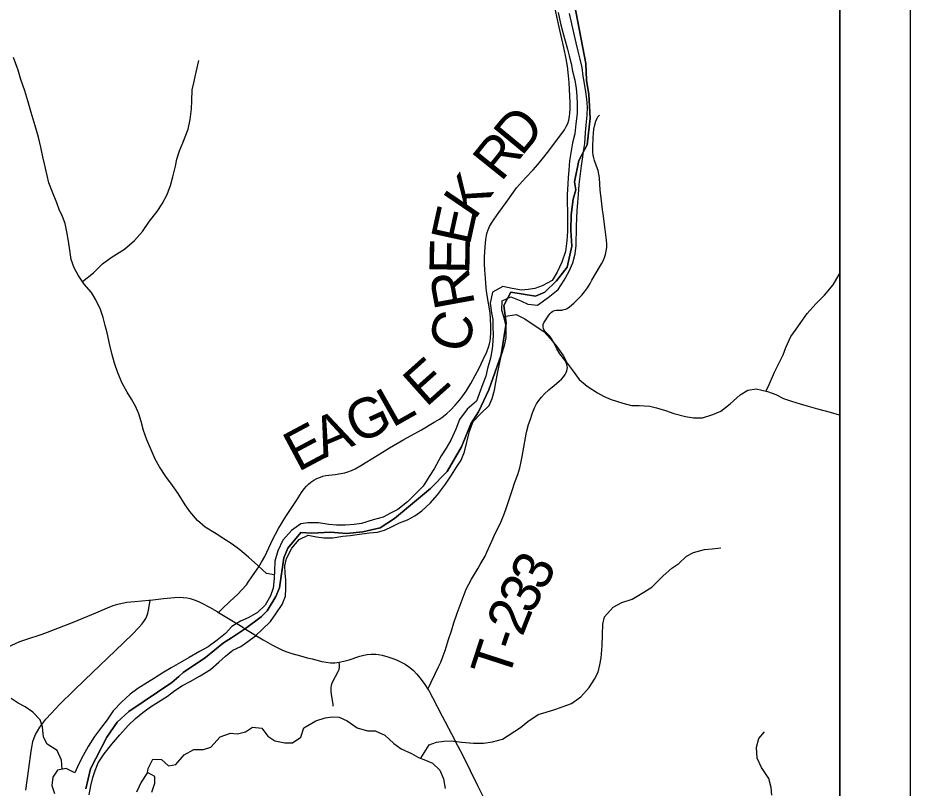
# Model space of a CAD drawing. Extents: x 0 to 34, y 0 to 22.
# Drawn here: x 7.947 to 9.214, y 15.927 to 17.022 of the extents above; entities that cross this region are included whole.
import ezdxf

# ---------------------------------------------------------------- set-up
doc = ezdxf.new("R2010")
doc.units = 0
for name, color, linetype in [('Default', 7, 'Continuous'), ('GM_X_County_Road', 7, 'Continuous'), ('GM_X_Minor_River', 7, 'Continuous'), ('GM_X_Township_Road', 7, 'Continuous'), ('GM_X_Township_Road_Text', 7, 'Continuous'), ('SH_Cut_Line', 7, 'Continuous'), ('SH_Data', 7, 'Continuous')]:
    doc.layers.add(name, color=color, linetype=linetype)

msp = doc.modelspace()

# ---------------------------------------------------------------- linework, layer by layer
at = {"layer": 'Default'}
for points in [[(9.1142, 14.0996), (9.1142, 17.7402)], [(8.735, 17.0537), (8.7536, 16.957), (8.7544, 16.9333), (8.7578, 16.9127), (8.7595, 16.8791), (8.7556, 16.8415), (8.7438, 16.8189), (8.7373, 16.7886), (8.7394, 16.7775), (8.7356, 16.7643), (8.7327, 16.742), (8.732, 16.72), (8.7335, 16.6972), (8.7271, 16.6673), (8.712, 16.6482), (8.6955, 16.6318), (8.6818, 16.6265), (8.6468, 16.632), (8.6371, 16.6129), (8.6404, 16.5881), (8.6333, 16.5428), (8.6156, 16.4931), (8.6011, 16.4621), (8.5903, 16.4448), (8.5769, 16.4122), (8.5565, 16.3771), (8.5331, 16.353), (8.4818, 16.3103), (8.4614, 16.297), (8.4368, 16.2914), (8.4136, 16.2889), (8.3908, 16.2909), (8.3642, 16.2897), (8.3485, 16.2907), (8.3303, 16.2683), (8.3243, 16.2543), (8.3186, 16.2117), (8.3132, 16.1995), (8.3007, 16.1792), (8.2924, 16.1706), (8.2699, 16.1539), (8.2503, 16.1408), (8.2386, 16.1335), (8.2134, 16.1129), (8.1813, 16.0914), (8.1752, 16.086), (8.1652, 16.0772), (8.1042, 16.0361), (8.0876, 16.0208), (8.0731, 15.9995), (8.0499, 15.9547), (8.0431, 15.9261)], [(8.0431, 15.9261), (8.0499, 15.9547), (8.0731, 15.9995), (8.0876, 16.0208), (8.1042, 16.0361), (8.1652, 16.0772), (8.1752, 16.086), (8.1813, 16.0914), (8.2134, 16.1129), (8.2386, 16.1335), (8.2503, 16.1408), (8.2699, 16.1539), (8.2924, 16.1706), (8.3007, 16.1792), (8.3132, 16.1995), (8.3186, 16.2117), (8.3243, 16.2543), (8.3303, 16.2683), (8.3485, 16.2907), (8.3642, 16.2897), (8.3908, 16.2909), (8.4136, 16.2889), (8.4368, 16.2914), (8.4614, 16.297), (8.4818, 16.3103), (8.5331, 16.353), (8.5565, 16.3771), (8.5769, 16.4122), (8.5903, 16.4448), (8.6011, 16.4621), (8.6156, 16.4931), (8.6333, 16.5428), (8.6404, 16.5881), (8.6371, 16.6129), (8.6468, 16.632), (8.6818, 16.6265), (8.6955, 16.6318), (8.712, 16.6482), (8.7271, 16.6673), (8.7335, 16.6972), (8.732, 16.72), (8.7327, 16.742), (8.7356, 16.7643), (8.7394, 16.7775), (8.7373, 16.7886), (8.7438, 16.8189), (8.7556, 16.8415), (8.7595, 16.8791), (8.7578, 16.9127), (8.7544, 16.9333), (8.7536, 16.957), (8.735, 17.0537)]]:
    msp.add_lwpolyline(points, dxfattribs=at)
at = {"layer": 'GM_X_County_Road'}
for points in [[(7.9354, 16.129), (7.938, 16.1303), (7.9432, 16.1327), (7.9496, 16.1354), (7.9578, 16.1383), (7.9814, 16.1462), (7.989, 16.149), (8.0265, 16.1637), (8.0575, 16.1764), (8.0741, 16.1835), (8.0823, 16.1866), (8.0889, 16.1887), (8.0949, 16.1902), (8.1017, 16.1913), (8.1129, 16.1926), (8.1327, 16.1943), (8.1348, 16.1945)], [(8.1348, 16.1945), (8.1536, 16.1966), (8.1691, 16.1982), (8.176, 16.1985), (8.1817, 16.1983), (8.1873, 16.1976), (8.1916, 16.1966), (8.197, 16.1949)], [(8.197, 16.1949), (8.2034, 16.1925), (8.208, 16.1903), (8.2189, 16.1843), (8.2296, 16.178), (8.2317, 16.1767)], [(8.2317, 16.1767), (8.2647, 16.1567), (8.2701, 16.1533)], [(8.2701, 16.1533), (8.2954, 16.1379), (8.3083, 16.1305), (8.316, 16.1265), (8.3216, 16.1239), (8.3273, 16.1216), (8.3361, 16.1186), (8.348, 16.1152), (8.3579, 16.1126)], [(8.3579, 16.1126), (8.3648, 16.1108), (8.3787, 16.1074), (8.3847, 16.1062), (8.3908, 16.1055), (8.3969, 16.1054), (8.4032, 16.1061)], [(8.4032, 16.1061), (8.4096, 16.1075), (8.4173, 16.1097), (8.4327, 16.1147), (8.4381, 16.1162), (8.4431, 16.1171), (8.4487, 16.1176), (8.455, 16.1177), (8.4588, 16.1173), (8.4644, 16.1161), (8.4722, 16.1139), (8.4793, 16.1115), (8.4857, 16.109), (8.4914, 16.1063), (8.4969, 16.1033), (8.5016, 16.1002), (8.5061, 16.0968), (8.5089, 16.0943), (8.5132, 16.0897), (8.5183, 16.0834), (8.5249, 16.0743), (8.529, 16.0679)], [(8.529, 16.0679), (8.5303, 16.0659), (8.5357, 16.0561), (8.5493, 16.0295), (8.5626, 16.0042), (8.5719, 15.9867), (8.5786, 15.9734), (8.5997, 15.9311), (8.6145, 15.9017)]]:
    msp.add_lwpolyline(points, dxfattribs=at)
at = {"layer": 'GM_X_Minor_River'}
for points in [[(8.714, 17.0294), (8.7176, 17.0137), (8.7205, 17.0027), (8.723, 16.9924), (8.7273, 16.9775), (8.7298, 16.968), (8.7327, 16.9569), (8.7348, 16.9459), (8.7377, 16.9333), (8.7398, 16.9215), (8.7408, 16.9112), (8.7413, 16.899), (8.7412, 16.8861), (8.7394, 16.871), (8.7381, 16.8569), (8.7345, 16.8441), (8.732, 16.83), (8.7303, 16.8187), (8.7294, 16.8054), (8.7285, 16.7948), (8.7279, 16.7853), (8.727, 16.7708), (8.7268, 16.761), (8.7274, 16.745), (8.7275, 16.7287), (8.7273, 16.718), (8.7264, 16.7051), (8.7247, 16.69), (8.7195, 16.6745), (8.7129, 16.6605), (8.7055, 16.6484), (8.6917, 16.6411), (8.681, 16.637), (8.6715, 16.6356), (8.6621, 16.635), (8.6488, 16.6371), (8.6356, 16.64), (8.6211, 16.6318), (8.6178, 16.6163), (8.6195, 16.6026)], [(8.6402, 16.5673), (8.6404, 16.5833), (8.6379, 16.5936), (8.6343, 16.6065), (8.6345, 16.6195), (8.6471, 16.6254), (8.6611, 16.6195), (8.6712, 16.6148), (8.6849, 16.6134), (8.6998, 16.6242), (8.7144, 16.6358), (8.7229, 16.649), (8.7299, 16.6618), (8.735, 16.6735), (8.7386, 16.6867), (8.7399, 16.6981), (8.7403, 16.7247), (8.7409, 16.7376), (8.7414, 16.7478), (8.742, 16.7596), (8.7429, 16.771), (8.7439, 16.785), (8.746, 16.8002), (8.7473, 16.8116), (8.7486, 16.8211), (8.7502, 16.8321), (8.7519, 16.8434), (8.7529, 16.859), (8.7538, 16.8692), (8.7552, 16.8836), (8.7557, 16.8947), (8.7551, 16.9064), (8.7537, 16.9167), (8.7516, 16.9285), (8.7499, 16.9388), (8.7482, 16.9514), (8.7457, 16.9632), (8.7428, 16.9746), (8.7396, 16.9864), (8.7371, 16.9986), (8.7335, 17.0131), (8.7303, 17.028)], [(8.3109, 16.2303), (8.2998, 16.2322), (8.2874, 16.2438), (8.2743, 16.2554), (8.262, 16.2658), (8.2511, 16.274), (8.2394, 16.2814), (8.2282, 16.2884), (8.2128, 16.2981), (8.2019, 16.3077), (8.1911, 16.3201), (8.1844, 16.33), (8.1744, 16.3457), (8.1666, 16.3573), (8.1569, 16.3699), (8.148, 16.3837), (8.1417, 16.3948), (8.1362, 16.4078), (8.13, 16.4224), (8.1253, 16.4353), (8.1217, 16.4483), (8.1184, 16.459), (8.1136, 16.4701), (8.1081, 16.48), (8.1018, 16.49), (8.0948, 16.5026), (8.0885, 16.5172), (8.0838, 16.5313), (8.0802, 16.545), (8.0774, 16.5568), (8.0734, 16.574), (8.0709, 16.5847), (8.0677, 16.5961), (8.0641, 16.6076), (8.0574, 16.6213), (8.0511, 16.6313), (8.0407, 16.6436), (8.0322, 16.6563), (8.0266, 16.6666), (8.0226, 16.6784), (8.0205, 16.6918), (8.0188, 16.7043), (8.0164, 16.7177), (8.0139, 16.7295), (8.0102, 16.7394), (8.0055, 16.7493), (8.0022, 16.7589), (7.996, 16.7742), (7.9908, 16.7875), (7.9883, 16.7978), (7.9844, 16.8146), (7.9823, 16.8241), (7.9794, 16.8379), (7.9762, 16.8523), (7.9715, 16.8684), (7.9658, 16.8874), (7.9611, 16.9038), (7.9567, 16.918), (7.9509, 16.9344), (7.9473, 16.9477), (7.9403, 16.9653)], [(8.0383, 16.6471), (8.0542, 16.6597), (8.0669, 16.6721), (8.0792, 16.6814), (8.0983, 16.6933), (8.1125, 16.7056), (8.1237, 16.7184), (8.1338, 16.7327), (8.1446, 16.7466), (8.1519, 16.7575), (8.1586, 16.7707), (8.1633, 16.7835), (8.1669, 16.796), (8.1705, 16.8112), (8.1726, 16.821), (8.1765, 16.8327), (8.1809, 16.8441), (8.1884, 16.8637), (8.1916, 16.8773), (8.1933, 16.8925), (8.1939, 16.9039), (8.1945, 16.9195), (8.1965, 16.9293), (8.2002, 16.9445), (8.2038, 16.9611)], [(9.0092, 16.4915), (9.0123, 16.4974), (9.0213, 16.5182), (9.0272, 16.5299), (9.0338, 16.543), (9.0378, 16.5536), (9.0448, 16.5691), (9.0522, 16.5796), (9.0611, 16.592), (9.0677, 16.6018), (9.08, 16.6153), (9.0927, 16.6277), (9.1047, 16.6423), (9.1136, 16.657), (9.1142, 16.6585)], [(8.6195, 16.6026), (8.6216, 16.5931), (8.6215, 16.582), (8.6217, 16.5725), (8.6212, 16.5623), (8.6203, 16.5513), (8.6182, 16.5384), (8.6138, 16.5236), (8.6114, 16.5127), (8.6074, 16.5017), (8.6019, 16.4874), (8.5983, 16.4771), (8.5849, 16.4659), (8.5741, 16.4509), (8.5689, 16.4373), (8.5619, 16.4218), (8.5549, 16.4102), (8.5479, 16.3996), (8.5382, 16.3811), (8.5308, 16.3699), (8.5226, 16.3563), (8.5122, 16.3458), (8.5003, 16.3342), (8.4865, 16.3234), (8.4762, 16.3178), (8.4655, 16.3123), (8.4514, 16.3083), (8.435, 16.3032), (8.4244, 16.3019), (8.4115, 16.3009), (8.3994, 16.3011), (8.3884, 16.302), (8.3736, 16.3041), (8.3588, 16.3043), (8.3489, 16.3026), (8.3352, 16.2933), (8.3232, 16.2794), (8.3158, 16.2643), (8.3118, 16.2499), (8.3112, 16.2366), (8.3107, 16.2249), (8.3093, 16.2112), (8.3058, 16.2006), (8.298, 16.1874), (8.2872, 16.177), (8.2746, 16.1696), (8.2631, 16.1644), (8.2505, 16.157), (8.2417, 16.1472), (8.2298, 16.1375), (8.2171, 16.1282), (8.2049, 16.1212), (8.19, 16.1127), (8.1777, 16.1056), (8.1647, 16.0982), (8.154, 16.0919), (8.141, 16.0837), (8.1307, 16.0774), (8.1173, 16.0689), (8.1062, 16.0607), (8.0939, 16.0495), (8.0823, 16.0371), (8.0734, 16.0243), (8.0653, 16.0138), (8.0556, 16.0006), (8.0467, 15.9863), (8.0397, 15.9735), (8.0334, 15.9618), (8.0276, 15.949), (8.0155, 15.9549), (8.003, 15.9528), (7.9964, 15.9426), (7.9951, 15.9309), (7.9987, 15.9194)], [(8.6369, 16.5973), (8.6547, 16.6002), (8.6671, 16.5943), (8.6788, 16.5862), (8.6938, 16.5761), (8.7035, 16.5657), (8.7117, 16.5553), (8.7214, 16.5422), (8.7269, 16.5311), (8.734, 16.5215), (8.744, 16.5077), (8.7556, 16.4984), (8.7699, 16.4891), (8.7797, 16.4836), (8.7895, 16.4797), (8.8061, 16.4745), (8.8185, 16.4709), (8.8292, 16.4708), (8.8443, 16.4702), (8.8541, 16.4678), (8.8666, 16.4638), (8.8783, 16.4598), (8.8949, 16.4554), (8.9063, 16.4533), (8.9192, 16.4535), (8.934, 16.4583), (8.9451, 16.463), (8.9585, 16.4731), (8.9727, 16.4862), (8.9838, 16.4929), (8.9956, 16.4946), (9.0115, 16.4909), (9.0235, 16.4866), (9.0341, 16.4811), (9.0458, 16.4772), (9.0578, 16.4732), (9.0695, 16.47), (9.0828, 16.466), (9.1005, 16.4616), (9.1134, 16.4579), (9.1142, 16.4576)], [(8.048, 15.9179), (8.0504, 15.9304), (8.0533, 15.9422), (8.0564, 15.9524), (8.0608, 15.963), (8.0693, 15.9761), (8.0801, 15.9896), (8.0917, 16.0032), (8.1032, 16.0163), (8.1136, 16.026), (8.124, 16.0346), (8.1351, 16.0428), (8.1466, 16.0498), (8.1592, 16.058), (8.1699, 16.0658), (8.1807, 16.0733), (8.1914, 16.0788), (8.2059, 16.0866), (8.2204, 16.0959), (8.232, 16.1064), (8.2416, 16.1146), (8.2523, 16.1232), (8.2634, 16.1287), (8.2733, 16.1354), (8.2844, 16.1436), (8.2944, 16.1529), (8.3056, 16.1642), (8.313, 16.1751), (8.3223, 16.1882), (8.327, 16.1999), (8.3275, 16.211), (8.3273, 16.2227), (8.3263, 16.2326), (8.3261, 16.2433), (8.3281, 16.2535), (8.3359, 16.2682), (8.3464, 16.2806), (8.359, 16.2869), (8.3711, 16.2844), (8.3813, 16.2827), (8.3942, 16.2829), (8.4082, 16.2854), (8.4189, 16.2864), (8.4322, 16.2881), (8.4462, 16.2898), (8.4576, 16.2908), (8.4675, 16.294), (8.4786, 16.2992), (8.4889, 16.304), (8.5003, 16.3087), (8.5106, 16.3143), (8.5206, 16.3214), (8.5325, 16.3322), (8.5426, 16.3438), (8.5541, 16.3593), (8.5627, 16.3721), (8.5697, 16.3833), (8.5763, 16.3935), (8.581, 16.4052), (8.5882, 16.4347), (8.5934, 16.448), (8.6038, 16.4592), (8.6164, 16.4708), (8.6204, 16.481), (8.6236, 16.4927), (8.6256, 16.5037), (8.6277, 16.5143), (8.6305, 16.528), (8.6338, 16.5431), (8.6378, 16.556), (8.6402, 16.5673)], [(8.519, 15.9697), (8.5309, 15.9888), (8.5416, 15.9925), (8.5519, 15.9942), (8.5621, 15.9945), (8.5773, 15.9927), (8.5939, 15.9913), (8.6083, 15.9911), (8.6209, 15.9928), (8.6353, 15.9968), (8.6606, 16.0132), (8.671, 16.0221), (8.6859, 16.0318), (8.6973, 16.0351), (8.711, 16.0394), (8.7213, 16.0431), (8.7331, 16.0475), (8.7462, 16.0571), (8.7581, 16.0703), (8.7659, 16.0823), (8.7709, 16.0921), (8.7734, 16.1023), (8.7754, 16.1122), (8.7768, 16.1293), (8.777, 16.1452), (8.7776, 16.16), (8.7801, 16.1706), (8.7924, 16.1845), (8.8046, 16.1908), (8.8191, 16.1959), (8.8359, 16.2055), (8.8474, 16.2126), (8.8632, 16.2291), (8.8755, 16.2399), (8.8854, 16.2466), (8.8966, 16.2567), (8.9065, 16.2619), (8.9221, 16.2662), (8.9331, 16.2672), (8.9453, 16.2689)], [(8.0097, 15.9539), (8.0089, 15.9671), (8.0026, 15.9809), (7.9883, 15.9898), (7.9832, 15.9998), (7.9815, 16.0143), (7.9782, 16.0242), (7.9682, 16.0353), (7.9573, 16.0427), (7.9471, 16.0478), (7.937, 16.0544)], [(8.1307, 15.9494), (8.1319, 15.9551), (8.1382, 15.9683), (8.1507, 15.9681), (8.1608, 15.9588), (8.1711, 15.9606), (8.183, 15.9745), (8.1968, 15.9823), (8.2104, 15.9821), (8.2207, 15.9853), (8.2342, 16), (8.2487, 16.0054), (8.2589, 16.0045), (8.2703, 16.0074), (8.2799, 16.0141), (8.2935, 16.0124), (8.3017, 16.0013), (8.3119, 15.9946), (8.3258, 15.9914), (8.3368, 15.9916), (8.3487, 15.9998), (8.3531, 16.0127), (8.3699, 16.0231), (8.3832, 16.027), (8.3931, 16.0284), (8.4033, 16.0279), (8.4143, 16.0228), (8.4289, 16.0131), (8.4436, 16.0087), (8.4543, 16.0085), (8.4678, 16.0023), (8.4809, 15.9907), (8.491, 15.9829), (8.5061, 15.9763), (8.5159, 15.9708), (8.5257, 15.9672), (8.5359, 15.9625), (8.5463, 15.9529), (8.5511, 15.9403), (8.5539, 15.9266)], [(9.0179, 15.9172), (9.0166, 15.9283), (9.0133, 15.9408), (9.0029, 15.9566), (8.9971, 15.9696), (8.9958, 15.9855), (8.9994, 15.9976), (9.0075, 16.0074)], [(8.1371, 15.9216), (8.1411, 15.9344), (8.1412, 15.9439), (8.1307, 15.9494), (8.1218, 15.9355), (8.1151, 15.9215)]]:
    msp.add_lwpolyline(points, dxfattribs=at)
at = {"layer": 'GM_X_Township_Road'}
for points in [[(8.2317, 16.1767), (8.2371, 16.1818), (8.248, 16.1923), (8.2593, 16.203), (8.2648, 16.2088), (8.2713, 16.2163), (8.274, 16.2198), (8.2792, 16.2275), (8.2866, 16.2382), (8.2891, 16.2418), (8.293, 16.2481), (8.2974, 16.2563), (8.303, 16.2687), (8.3089, 16.2809), (8.3125, 16.2879), (8.3169, 16.296), (8.3273, 16.313), (8.3396, 16.3317), (8.3424, 16.3358), (8.3497, 16.3474), (8.3533, 16.3524), (8.3566, 16.3562), (8.3596, 16.3592), (8.363, 16.362), (8.3671, 16.3647), (8.3715, 16.3671), (8.3766, 16.3693), (8.3801, 16.3705), (8.3844, 16.3714), (8.3973, 16.373), (8.4053, 16.3741), (8.4114, 16.3754), (8.4156, 16.3766), (8.4208, 16.3786), (8.4258, 16.381), (8.434, 16.3855), (8.4572, 16.4), (8.4747, 16.4106), (8.4951, 16.4225), (8.5199, 16.4366), (8.5383, 16.4471), (8.5457, 16.4517), (8.5508, 16.4552), (8.5561, 16.4595), (8.5611, 16.4642), (8.568, 16.4713), (8.5745, 16.4789), (8.579, 16.4848), (8.5836, 16.4914), (8.59, 16.5021), (8.5964, 16.5135), (8.6019, 16.5239), (8.6079, 16.5362), (8.6127, 16.547), (8.6154, 16.5539), (8.6168, 16.5587), (8.6176, 16.5623), (8.6183, 16.5672), (8.6188, 16.574), (8.6188, 16.584), (8.6183, 16.5939), (8.6174, 16.6026), (8.613, 16.6302), (8.612, 16.6382), (8.6109, 16.6517), (8.61, 16.6634), (8.6096, 16.6721), (8.6097, 16.682), (8.6105, 16.6963), (8.6114, 16.7068), (8.6122, 16.7124), (8.6132, 16.7166), (8.6146, 16.7207), (8.6166, 16.7253), (8.6193, 16.7301), (8.6231, 16.7358), (8.6301, 16.7453), (8.6404, 16.7594), (8.6507, 16.7741), (8.6552, 16.7801), (8.6591, 16.7849), (8.668, 16.7944), (8.6786, 16.8058), (8.6851, 16.8132), (8.6938, 16.8238), (8.6992, 16.8305), (8.7195, 16.8573), (8.7234, 16.8629), (8.7258, 16.8672), (8.7278, 16.8718), (8.7293, 16.8765), (8.7304, 16.8814), (8.731, 16.8863), (8.7313, 16.8925), (8.7312, 16.9012), (8.7297, 16.9298), (8.7286, 16.944), (8.7275, 16.9533), (8.7257, 16.9637), (8.7224, 16.9795), (8.7167, 17.0044), (8.7101, 17.0344)], [(8.7634, 16.8371), (8.7634, 16.8388), (8.7637, 16.8512), (8.7643, 16.858), (8.7651, 16.8636), (8.7663, 16.8697), (8.7678, 16.8751), (8.7694, 16.8791), (8.7706, 16.8813), (8.7718, 16.8827), (8.7727, 16.8835)], [(8.7621, 16.6489), (8.7666, 16.6569), (8.7681, 16.6596), (8.7758, 16.6724), (8.7784, 16.6774), (8.7801, 16.6814), (8.7815, 16.6855), (8.7826, 16.6904), (8.7832, 16.6953), (8.7834, 16.7002), (8.783, 16.7058), (8.7811, 16.7212), (8.778, 16.7434), (8.7774, 16.7488), (8.7752, 16.7659), (8.774, 16.777), (8.7729, 16.7943), (8.7722, 16.7999), (8.7712, 16.8047), (8.7689, 16.8111), (8.7657, 16.8192), (8.7647, 16.8228), (8.7639, 16.8264), (8.7635, 16.8308), (8.7634, 16.8371)], [(8.529, 16.0679), (8.5308, 16.0716), (8.5336, 16.078), (8.5388, 16.0885), (8.5444, 16.0996), (8.5474, 16.1064), (8.551, 16.115), (8.5536, 16.1226), (8.5586, 16.1385), (8.5625, 16.1509), (8.5662, 16.1622), (8.5707, 16.1757), (8.5806, 16.2025), (8.5836, 16.21), (8.5871, 16.2173), (8.591, 16.2243), (8.6004, 16.24), (8.6036, 16.2452), (8.6103, 16.257), (8.613, 16.2625), (8.6202, 16.2783), (8.6227, 16.2846), (8.6256, 16.2908), (8.6317, 16.3029), (8.6353, 16.3108), (8.638, 16.3178), (8.6409, 16.326), (8.6487, 16.3502), (8.6528, 16.362), (8.6568, 16.3731), (8.6597, 16.3826), (8.6614, 16.3892), (8.6631, 16.3983), (8.6676, 16.4252), (8.6693, 16.4331), (8.6722, 16.4439), (8.6743, 16.4503), (8.6779, 16.4606), (8.6808, 16.4678), (8.6836, 16.4732), (8.6866, 16.4779), (8.6904, 16.4827), (8.695, 16.4877), (8.7009, 16.4932), (8.7085, 16.4996), (8.7157, 16.5055), (8.7188, 16.5085), (8.7221, 16.5122), (8.7243, 16.5152), (8.7258, 16.5179), (8.7266, 16.5202), (8.7271, 16.5226), (8.7273, 16.5251), (8.7271, 16.5269), (8.7266, 16.5293), (8.7254, 16.5322), (8.7235, 16.5353), (8.7168, 16.5443), (8.7137, 16.549), (8.7122, 16.5517), (8.7087, 16.5589), (8.7062, 16.5639), (8.7045, 16.5666), (8.7023, 16.5695), (8.6954, 16.5767), (8.694, 16.5788), (8.6932, 16.5805), (8.6928, 16.5823), (8.6927, 16.5841), (8.693, 16.5859), (8.694, 16.5882), (8.7009, 16.5993), (8.7028, 16.6018), (8.7046, 16.6034), (8.7067, 16.6048), (8.709, 16.6058), (8.7114, 16.6063), (8.7151, 16.6065), (8.7195, 16.6066), (8.7225, 16.6072), (8.7249, 16.6079), (8.7271, 16.609), (8.7302, 16.6111), (8.7364, 16.6163), (8.7418, 16.6214), (8.7478, 16.6277), (8.7518, 16.6325), (8.7557, 16.6381), (8.7596, 16.6445), (8.7621, 16.6489)], [(7.958, 15.9242), (7.9621, 15.955), (7.9654, 15.9796), (7.9668, 15.9876), (7.9682, 15.9936), (7.97, 15.9989), (7.9719, 16.0035), (7.9745, 16.0084), (7.9778, 16.0137), (7.9822, 16.0197), (7.9865, 16.0251), (7.9939, 16.0335), (8.0064, 16.0464), (8.0258, 16.0656), (8.0418, 16.0812), (8.0849, 16.1225), (8.1095, 16.1462), (8.1187, 16.1555), (8.1228, 16.1601), (8.1258, 16.1641), (8.1284, 16.1684), (8.13, 16.1717), (8.1315, 16.1757), (8.1325, 16.18), (8.1334, 16.1855), (8.1348, 16.1945)], [(8.3948, 16.0439), (8.3945, 16.0463), (8.3923, 16.0609), (8.3918, 16.0652), (8.3917, 16.0701), (8.392, 16.0732), (8.3925, 16.0756), (8.3935, 16.0779), (8.4018, 16.0931), (8.4029, 16.096), (8.4036, 16.099), (8.4036, 16.1021), (8.4032, 16.1061)]]:
    msp.add_lwpolyline(points, dxfattribs=at)
at = {"layer": 'SH_Cut_Line'}
msp.add_lwpolyline([(9.1142, 14.0996), (9.1142, 20.8996), (2.3142, 20.8996)], dxfattribs=at)
at = {"layer": 'SH_Data'}
for p, q in [((9.2142, 20.9996), (9.2142, 13.9996)), ((9.1142, 20.8996), (9.1142, 14.0996))]:
    msp.add_line(p, q, dxfattribs=at)

# ---------------------------------------------------------------- texts
at = {"layer": 'GM_X_Township_Road_Text'}
for s, rotation, p in [('D', 50.3747, (8.6622, 16.8239)), ('R', 51.2439, (8.6332, 16.7877)), ('K', 55.7103, (8.5953, 16.7332)), ('E', 77.6213, (8.5885, 16.697)), ('E', 88.9242, (8.588, 16.6574)), ('R', 100.3579, (8.5962, 16.6145)), ('C', 76.6954, (8.5848, 16.5436)), ('E', 41.8106, (8.5266, 16.4675)), ('L', 29.4269, (8.4787, 16.4388)), ('G', 24.6338, (8.4286, 16.4156)), ('A', 22.9869, (8.381, 16.3954)), ('E', 28.0707, (8.3447, 16.376)), ('3', 63.6099, (8.6941, 16.2055)), ('3', 60.5817, (8.6754, 16.1721)), ('2', 68.445, (8.6634, 16.1414)), ('-', 71.014, (8.6561, 16.12)), ('T', 72.0058, (8.643, 16.0798))]:
    msp.add_text(s, height=0.0568, rotation=rotation, dxfattribs=at).set_placement(p)

doc.saveas('drawing.dxf')
